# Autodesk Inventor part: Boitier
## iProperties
Author: Philippe
Shininess: 20.0
Angle Display Precision: 2
Document Length Units: 11269
Document Angle Units: 11283
Document Time Units: 11279
Document Mass Units: 11290
Document Length Units Precision: 3
Document Angle Units Precision: 2
Compacted: False
PropertySet Name: _Private Model Information
Created: 2002-01
Part Number: Boitier
Project: Servo
Material: Par défaut
Document SubType Name: Modélisation
Designer: Philippe
Control State: 0
Master: False
Checked Out: False
PropertySet Name: Design Tracking Control
Density: 0.0
Volumn: 0.0
Area: 0.0
PropertySet Name: Model Information
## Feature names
1. Extrusion1
2. Congé1 [Fillet]
3. Coque1
4. Perçage1 [Hole]
5. Extrusion3
6. Extrusion6
7. Perçage2 [Hole]
8. Extrusion4
9. Extrusion5
10. Extrusion7
11. Extrusion8
12. Extrusion9
